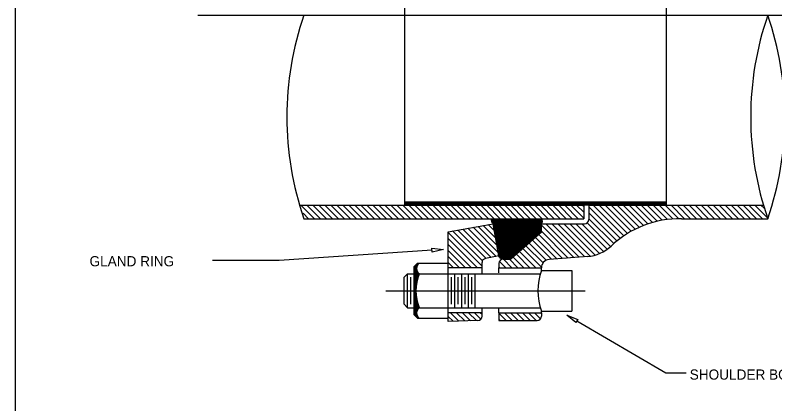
# Model space of a CAD drawing. Extents: x 2147138 to 2147698, y 2147153 to 2147515.
# Drawn here: x 2147558.3 to 2147647.9, y 2147251.8 to 2147297.7 of the extents above; entities that cross this region are included whole.
import ezdxf

# ---------------------------------------------------------------- set-up
doc = ezdxf.new("R2010")
doc.units = 0
for name, color, linetype in [('EQPM', 7, 'Continuous'), ('G-ANNO-TEXT-LW10', 7, 'Continuous'), ('G-DETL-CNTR', 7, 'Continuous'), ('G-DETL-LW10', 7, 'Continuous'), ('G-DETL-PATT', 7, 'Continuous'), ('PATTERN_CLASS', 7, 'Continuous')]:
    doc.layers.add(name, color=color, linetype=linetype)

msp = doc.modelspace()

# ---------------------------------------------------------------- linework, layer by layer
at = {"layer": 'EQPM'}
for p, q in [((2147604.195, 2147275.672), (2147604.195, 2147275.272)), ((2147604.195, 2147275.672), (2147635.045, 2147275.672)), ((2147604.195, 2147275.654), (2147635.045, 2147275.654)), ((2147604.195, 2147275.604), (2147635.045, 2147275.604)), ((2147604.195, 2147275.554), (2147635.045, 2147275.554)), ((2147604.195, 2147275.504), (2147635.045, 2147275.504)), ((2147604.195, 2147275.454), (2147635.045, 2147275.454)), ((2147604.195, 2147275.404), (2147635.045, 2147275.404)), ((2147604.195, 2147275.354), (2147635.045, 2147275.354)), ((2147604.195, 2147275.304), (2147635.045, 2147275.304)), ((2147625.93, 2147275.272), (2147625.33, 2147275.272)), ((2147635.045, 2147275.672), (2147635.045, 2147275.272))]:
    msp.add_line(p, q, dxfattribs=at)
at = {"layer": 'G-ANNO-TEXT-LW10'}
for p, q in [((2147607.435, 2147269.953), (2147589.386, 2147268.72)), ((2147589.386, 2147268.72), (2147581.522, 2147268.72)), ((2147624.501, 2147261.603), (2147635.011, 2147255.478)), ((2147635.011, 2147255.478), (2147637.397, 2147255.478))]:
    msp.add_line(p, q, dxfattribs=at)
for points in [[(2147607.42, 2147270.175), (2147608.767, 2147270.044), (2147607.45, 2147269.731)], [(2147624.389, 2147261.41), (2147623.347, 2147262.275), (2147624.613, 2147261.795)]]:
    msp.add_lwpolyline(points, close=True, dxfattribs=at)
at = {"layer": 'G-DETL-CNTR'}
for p, q in [((2147579.795, 2147297.672), (2147660.381, 2147297.672)), ((2147601.998, 2147265.172), (2147625.503, 2147265.172))]:
    msp.add_line(p, q, dxfattribs=at)
at = {"layer": 'G-DETL-LW10'}
for p, q in [((2147591.791, 2147275.272), (2147625.33, 2147275.272)), ((2147625.33, 2147275.272), (2147625.33, 2147273.672)), ((2147625.93, 2147275.272), (2147646.527, 2147275.272)), ((2147625.93, 2147275.272), (2147625.93, 2147273.572)), ((2147592.302, 2147273.672), (2147625.33, 2147273.672)), ((2147609.33, 2147272.135), (2147614.663, 2147273.075)), ((2147614.459, 2147273.559), (2147614.464, 2147273.581)), ((2147614.459, 2147273.521), (2147614.459, 2147273.559)), ((2147614.466, 2147273.467), (2147614.459, 2147273.521)), ((2147614.464, 2147273.581), (2147614.478, 2147273.594)), ((2147614.479, 2147273.36), (2147614.466, 2147273.467)), ((2147614.478, 2147273.594), (2147614.498, 2147273.597)), ((2147614.504, 2147273.279), (2147614.479, 2147273.36)), ((2147614.498, 2147273.597), (2147614.519, 2147273.598)), ((2147614.539, 2147273.202), (2147614.504, 2147273.279)), ((2147614.519, 2147273.598), (2147620.341, 2147273.598)), ((2147614.59, 2147273.143), (2147614.539, 2147273.202)), ((2147614.628, 2147273.113), (2147614.59, 2147273.143)), ((2147614.671, 2147273.1), (2147614.628, 2147273.113)), ((2147615.33, 2147269.292), (2147614.663, 2147273.075)), ((2147615.357, 2147269.276), (2147614.671, 2147273.1)), ((2147620.39, 2147273.179), (2147620.304, 2147273.084)), ((2147620.304, 2147273.084), (2147620.305, 2147272.084)), ((2147620.33, 2147273.072), (2147625.43, 2147273.072)), ((2147620.33, 2147272.072), (2147620.33, 2147273.072)), ((2147620.341, 2147273.598), (2147620.395, 2147273.52)), ((2147620.422, 2147273.261), (2147620.39, 2147273.179)), ((2147620.395, 2147273.52), (2147620.431, 2147273.388)), ((2147620.431, 2147273.388), (2147620.422, 2147273.261)), ((2147636.86, 2147273.672), (2147647.038, 2147273.672)), ((2147609.33, 2147267.892), (2147609.33, 2147272.135)), ((2147620.305, 2147272.084), (2147616.725, 2147268.907)), ((2147620.33, 2147272.072), (2147616.73, 2147268.892)), ((2147615.33, 2147269.292), (2147613.732, 2147268.973)), ((2147615.314, 2147269.268), (2147615.357, 2147269.276)), ((2147615.314, 2147269.224), (2147615.314, 2147269.268)), ((2147615.334, 2147269.165), (2147615.314, 2147269.224)), ((2147615.373, 2147269.098), (2147615.334, 2147269.165)), ((2147615.456, 2147269.027), (2147615.373, 2147269.098)), ((2147615.559, 2147268.964), (2147615.456, 2147269.027)), ((2147615.642, 2147268.928), (2147615.559, 2147268.964)), ((2147615.717, 2147268.908), (2147615.642, 2147268.928)), ((2147616.725, 2147268.907), (2147615.717, 2147268.908)), ((2147615.83, 2147268.892), (2147616.73, 2147268.892)), ((2147625.793, 2147269.207), (2147621.252, 2147268.865)), ((2147605.33, 2147268.022), (2147605.73, 2147268.422)), ((2147605.33, 2147262.322), (2147605.33, 2147268.022)), ((2147605.73, 2147268.422), (2147609.33, 2147268.422)), ((2147609.33, 2147261.922), (2147609.33, 2147268.422)), ((2147613.33, 2147267.892), (2147609.33, 2147267.892)), ((2147613.33, 2147267.892), (2147613.33, 2147268.483)), ((2147613.33, 2147267.172), (2147613.33, 2147267.892)), ((2147615.33, 2147268.392), (2147615.33, 2147267.892)), ((2147615.33, 2147267.892), (2147620.33, 2147267.892)), ((2147615.33, 2147267.292), (2147615.33, 2147267.892)), ((2147620.33, 2147267.572), (2147620.33, 2147267.868)), ((2147604.13, 2147266.772), (2147604.53, 2147267.172)), ((2147604.53, 2147263.172), (2147604.53, 2147267.172)), ((2147604.53, 2147267.172), (2147605.33, 2147267.172)), ((2147605.93, 2147267.172), (2147609.33, 2147267.172)), ((2147609.33, 2147267.172), (2147620.206, 2147267.172)), ((2147610.13, 2147263.172), (2147610.13, 2147267.172)), ((2147610.93, 2147263.172), (2147610.93, 2147267.172)), ((2147611.73, 2147263.172), (2147611.73, 2147267.172)), ((2147612.53, 2147263.172), (2147612.53, 2147267.172)), ((2147620.33, 2147267.572), (2147623.93, 2147267.572)), ((2147623.93, 2147267.572), (2147623.93, 2147262.772)), ((2147604.13, 2147263.572), (2147604.13, 2147266.772)), ((2147604.93, 2147263.572), (2147604.93, 2147266.772)), ((2147609.73, 2147263.572), (2147609.73, 2147266.772)), ((2147610.53, 2147263.572), (2147610.53, 2147266.772)), ((2147611.33, 2147263.572), (2147611.33, 2147266.772)), ((2147612.13, 2147263.572), (2147612.13, 2147266.772)), ((2147604.53, 2147263.172), (2147604.13, 2147263.572)), ((2147604.53, 2147263.172), (2147605.33, 2147263.172)), ((2147605.33, 2147262.322), (2147605.73, 2147261.922)), ((2147605.93, 2147263.172), (2147609.33, 2147263.172)), ((2147609.33, 2147263.172), (2147620.206, 2147263.172)), ((2147613.33, 2147262.572), (2147609.33, 2147262.572)), ((2147609.33, 2147261.552), (2147609.33, 2147262.572)), ((2147613.33, 2147262.572), (2147613.33, 2147263.172)), ((2147613.33, 2147262.158), (2147613.33, 2147262.572)), ((2147615.33, 2147262.572), (2147615.33, 2147263.172)), ((2147615.33, 2147262.572), (2147620.33, 2147262.572)), ((2147615.33, 2147262.572), (2147615.33, 2147261.672)), ((2147620.33, 2147262.572), (2147620.33, 2147262.772)), ((2147620.33, 2147262.772), (2147623.93, 2147262.772)), ((2147620.33, 2147262.572), (2147620.33, 2147262.172)), ((2147605.73, 2147261.922), (2147609.33, 2147261.922)), ((2147612.845, 2147261.658), (2147609.33, 2147261.552)), ((2147615.33, 2147261.672), (2147619.83, 2147261.672))]:
    msp.add_line(p, q, dxfattribs=at)
for centre, radius, start, end in [((2147627.142, 2147285.672), 36.849, 160.99467, 199.00533), ((2147627.142, 2147285.672), 36.849, 160.99467, 199.00533), ((2147681.878, 2147285.672), 36.849, 160.99467, 199.00533), ((2147612.198, 2147285.672), 36.849, 340.99467, 19.00533), ((2147625.43, 2147273.572), 0.5, 270, 0), ((2147636.69, 2147261.787), 11.886, 89.17883, 133.23579), ((2147625.43, 2147273.692), 4.5, 274.61829, 313.84535), ((2147613.83, 2147268.483), 0.5, 101.30993, 180), ((2147615.83, 2147268.392), 0.5, 90, 180), ((2147621.33, 2147267.868), 1, 94.4928, 180), ((2147606.401, 2147267.797), 0.783, 127.00306, 232.99694), ((2147610.73, 2147265.172), 5.2, 157.38014, 202.61986), ((2147627.33, 2147265.172), 7.4, 161.07536, 198.92464), ((2147606.401, 2147262.547), 0.783, 127.00306, 232.99694), ((2147612.83, 2147262.158), 0.5, 271.71836, 0), ((2147619.83, 2147262.172), 0.5, 270, 0)]:
    msp.add_arc(centre, radius, start, end, dxfattribs=at)
at = {"layer": 'G-DETL-PATT'}
for p, q in [((2147604.195, 2147319.672), (2147604.195, 2147275.672)), ((2147635.045, 2147319.672), (2147635.045, 2147275.653)), ((2147591.967, 2147275.272), (2147593.567, 2147273.672)), ((2147592.675, 2147275.272), (2147594.275, 2147273.672)), ((2147593.382, 2147275.272), (2147594.982, 2147273.672)), ((2147594.089, 2147275.272), (2147595.689, 2147273.672)), ((2147594.796, 2147275.272), (2147596.396, 2147273.672)), ((2147595.503, 2147275.272), (2147597.103, 2147273.672)), ((2147596.21, 2147275.272), (2147597.81, 2147273.672)), ((2147596.917, 2147275.272), (2147598.517, 2147273.672)), ((2147597.624, 2147275.272), (2147599.224, 2147273.672)), ((2147598.331, 2147275.272), (2147599.931, 2147273.672)), ((2147599.039, 2147275.272), (2147600.639, 2147273.672)), ((2147599.746, 2147275.272), (2147601.346, 2147273.672)), ((2147600.453, 2147275.272), (2147602.053, 2147273.672)), ((2147601.16, 2147275.272), (2147602.76, 2147273.672)), ((2147601.867, 2147275.272), (2147603.467, 2147273.672)), ((2147602.574, 2147275.272), (2147604.174, 2147273.672)), ((2147603.281, 2147275.272), (2147604.881, 2147273.672)), ((2147603.988, 2147275.272), (2147605.588, 2147273.672)), ((2147604.695, 2147275.272), (2147606.295, 2147273.672)), ((2147605.403, 2147275.272), (2147607.003, 2147273.672)), ((2147606.11, 2147275.272), (2147607.71, 2147273.672)), ((2147606.817, 2147275.272), (2147608.417, 2147273.672)), ((2147607.524, 2147275.272), (2147609.124, 2147273.672)), ((2147608.231, 2147275.272), (2147609.831, 2147273.672)), ((2147608.938, 2147275.272), (2147610.538, 2147273.672)), ((2147609.645, 2147275.272), (2147611.245, 2147273.672)), ((2147610.352, 2147275.272), (2147611.952, 2147273.672)), ((2147611.059, 2147275.272), (2147612.659, 2147273.672)), ((2147611.766, 2147275.272), (2147613.366, 2147273.672)), ((2147612.474, 2147275.272), (2147614.074, 2147273.672)), ((2147613.181, 2147275.272), (2147614.781, 2147273.672)), ((2147613.888, 2147275.272), (2147615.488, 2147273.672)), ((2147614.595, 2147275.272), (2147616.195, 2147273.672)), ((2147615.302, 2147275.272), (2147616.902, 2147273.672)), ((2147616.009, 2147275.272), (2147617.609, 2147273.672)), ((2147616.716, 2147275.272), (2147618.316, 2147273.672)), ((2147617.423, 2147275.272), (2147619.023, 2147273.672)), ((2147618.13, 2147275.272), (2147619.73, 2147273.672)), ((2147618.838, 2147275.272), (2147620.438, 2147273.672)), ((2147619.545, 2147275.272), (2147621.145, 2147273.672)), ((2147620.252, 2147275.272), (2147621.852, 2147273.672)), ((2147620.959, 2147275.272), (2147622.559, 2147273.672)), ((2147621.666, 2147275.272), (2147623.266, 2147273.672)), ((2147622.373, 2147275.272), (2147623.973, 2147273.672)), ((2147623.08, 2147275.272), (2147624.68, 2147273.672)), ((2147623.787, 2147275.272), (2147625.33, 2147273.729)), ((2147624.494, 2147275.272), (2147625.33, 2147274.437)), ((2147625.202, 2147275.272), (2147625.33, 2147275.144)), ((2147629.645, 2147271.361), (2147625.93, 2147275.077)), ((2147630.061, 2147271.653), (2147626.442, 2147275.272)), ((2147630.491, 2147271.93), (2147627.149, 2147275.272)), ((2147630.938, 2147272.19), (2147627.856, 2147275.272)), ((2147631.402, 2147272.433), (2147628.563, 2147275.272)), ((2147631.884, 2147272.659), (2147629.27, 2147275.272)), ((2147632.383, 2147272.866), (2147629.977, 2147275.272)), ((2147632.902, 2147273.054), (2147630.684, 2147275.272)), ((2147633.442, 2147273.221), (2147631.391, 2147275.272)), ((2147634.004, 2147273.366), (2147632.098, 2147275.272)), ((2147634.591, 2147273.487), (2147632.805, 2147275.272)), ((2147635.205, 2147273.58), (2147633.513, 2147275.272)), ((2147635.848, 2147273.644), (2147634.22, 2147275.272)), ((2147636.527, 2147273.673), (2147634.927, 2147275.272)), ((2147637.234, 2147273.672), (2147635.634, 2147275.272)), ((2147637.941, 2147273.672), (2147636.341, 2147275.272)), ((2147638.648, 2147273.672), (2147637.048, 2147275.272)), ((2147639.355, 2147273.672), (2147637.755, 2147275.272)), ((2147640.062, 2147273.672), (2147638.462, 2147275.272)), ((2147640.769, 2147273.672), (2147639.169, 2147275.272)), ((2147641.477, 2147273.672), (2147639.877, 2147275.272)), ((2147642.184, 2147273.672), (2147640.584, 2147275.272)), ((2147642.891, 2147273.672), (2147641.291, 2147275.272)), ((2147643.598, 2147273.672), (2147641.998, 2147275.272)), ((2147644.305, 2147273.672), (2147642.705, 2147275.272)), ((2147645.012, 2147273.672), (2147643.412, 2147275.272)), ((2147645.719, 2147273.672), (2147644.119, 2147275.272)), ((2147646.426, 2147273.672), (2147644.826, 2147275.272)), ((2147646.988, 2147273.818), (2147645.533, 2147275.272)), ((2147646.65, 2147274.863), (2147646.241, 2147275.272)), ((2147592.23, 2147274.303), (2147592.86, 2147273.672)), ((2147629.246, 2147271.054), (2147625.93, 2147274.369)), ((2147614.582, 2147273.598), (2147614.582, 2147273.151)), ((2147614.707, 2147273.598), (2147614.707, 2147272.898)), ((2147614.832, 2147273.598), (2147614.832, 2147272.202)), ((2147614.957, 2147273.598), (2147614.957, 2147271.506)), ((2147615.082, 2147273.598), (2147615.082, 2147270.809)), ((2147615.207, 2147273.598), (2147615.207, 2147270.113)), ((2147615.332, 2147273.598), (2147615.332, 2147269.416)), ((2147615.457, 2147273.598), (2147615.457, 2147269.026)), ((2147615.582, 2147273.598), (2147615.582, 2147268.954)), ((2147615.707, 2147273.598), (2147615.707, 2147268.911)), ((2147615.832, 2147273.598), (2147615.832, 2147268.908)), ((2147615.957, 2147273.598), (2147615.957, 2147268.908)), ((2147616.082, 2147273.598), (2147616.082, 2147268.908)), ((2147616.207, 2147273.598), (2147616.207, 2147268.908)), ((2147616.332, 2147273.598), (2147616.332, 2147268.908)), ((2147616.457, 2147273.598), (2147616.457, 2147268.908)), ((2147616.582, 2147273.598), (2147616.582, 2147268.907)), ((2147616.707, 2147273.598), (2147616.707, 2147268.907)), ((2147616.832, 2147273.598), (2147616.832, 2147269.002)), ((2147616.957, 2147273.598), (2147616.957, 2147269.113)), ((2147617.082, 2147273.598), (2147617.082, 2147269.224)), ((2147617.207, 2147273.598), (2147617.207, 2147269.335)), ((2147617.332, 2147273.598), (2147617.332, 2147269.446)), ((2147617.457, 2147273.598), (2147617.457, 2147269.557)), ((2147617.582, 2147273.598), (2147617.582, 2147269.668)), ((2147617.707, 2147273.598), (2147617.707, 2147269.778)), ((2147617.832, 2147273.598), (2147617.832, 2147269.889)), ((2147617.957, 2147273.598), (2147617.957, 2147270)), ((2147618.082, 2147273.598), (2147618.082, 2147270.111)), ((2147618.207, 2147273.598), (2147618.207, 2147270.222)), ((2147618.332, 2147273.598), (2147618.332, 2147270.333)), ((2147618.457, 2147273.598), (2147618.457, 2147270.444)), ((2147618.582, 2147273.598), (2147618.582, 2147270.555)), ((2147618.707, 2147273.598), (2147618.707, 2147270.666)), ((2147618.832, 2147273.598), (2147618.832, 2147270.777)), ((2147618.957, 2147273.598), (2147618.957, 2147270.888)), ((2147619.082, 2147273.598), (2147619.082, 2147270.999)), ((2147619.207, 2147273.598), (2147619.207, 2147271.11)), ((2147619.332, 2147273.598), (2147619.332, 2147271.22)), ((2147619.457, 2147273.598), (2147619.457, 2147271.331)), ((2147619.582, 2147273.598), (2147619.582, 2147271.442)), ((2147619.707, 2147273.598), (2147619.707, 2147271.553)), ((2147619.832, 2147273.598), (2147619.832, 2147271.664)), ((2147619.957, 2147273.598), (2147619.957, 2147271.775)), ((2147620.082, 2147273.598), (2147620.082, 2147271.886)), ((2147620.207, 2147273.598), (2147620.207, 2147271.997)), ((2147620.332, 2147273.598), (2147620.332, 2147273.115)), ((2147624.803, 2147269.132), (2147620.863, 2147273.072)), ((2147625.461, 2147269.182), (2147621.57, 2147273.072)), ((2147626.106, 2147269.244), (2147622.278, 2147273.072)), ((2147626.686, 2147269.371), (2147622.985, 2147273.072)), ((2147627.206, 2147269.558), (2147623.692, 2147273.072)), ((2147627.678, 2147269.794), (2147624.399, 2147273.072)), ((2147628.105, 2147270.074), (2147625.106, 2147273.072)), ((2147628.491, 2147270.394), (2147625.72, 2147273.165)), ((2147628.861, 2147270.732), (2147625.93, 2147273.662)), ((2147609.861, 2147272.228), (2147613.383, 2147268.706)), ((2147610.462, 2147272.334), (2147613.808, 2147268.988)), ((2147611.063, 2147272.44), (2147614.398, 2147269.106)), ((2147611.664, 2147272.546), (2147614.987, 2147269.224)), ((2147612.265, 2147272.652), (2147615.267, 2147269.65)), ((2147612.866, 2147272.758), (2147615.116, 2147270.509)), ((2147613.468, 2147272.864), (2147614.964, 2147271.367)), ((2147614.069, 2147272.97), (2147614.813, 2147272.226)), ((2147624.146, 2147269.083), (2147620.33, 2147272.898)), ((2147623.488, 2147269.033), (2147620.33, 2147272.191)), ((2147609.33, 2147272.052), (2147613.33, 2147268.052)), ((2147609.33, 2147271.345), (2147612.783, 2147267.892)), ((2147622.173, 2147268.934), (2147619.642, 2147271.465)), ((2147622.831, 2147268.984), (2147620.018, 2147271.797)), ((2147609.33, 2147270.638), (2147612.075, 2147267.892)), ((2147620.525, 2147268.461), (2147618.516, 2147270.47)), ((2147620.915, 2147268.778), (2147618.892, 2147270.802)), ((2147621.516, 2147268.885), (2147619.267, 2147271.133)), ((2147609.33, 2147269.93), (2147611.368, 2147267.892)), ((2147619.679, 2147267.892), (2147617.765, 2147269.807)), ((2147620.333, 2147267.946), (2147618.141, 2147270.138)), ((2147609.33, 2147269.223), (2147610.661, 2147267.892)), ((2147615.332, 2147269.271), (2147615.332, 2147269.17)), ((2147616.144, 2147267.892), (2147615.396, 2147268.64)), ((2147616.851, 2147267.892), (2147615.851, 2147268.892)), ((2147617.558, 2147267.892), (2147616.558, 2147268.892)), ((2147618.265, 2147267.892), (2147617.014, 2147269.143)), ((2147618.972, 2147267.892), (2147617.39, 2147269.475)), ((2147605.357, 2147268.049), (2147605.357, 2147265.172)), ((2147605.407, 2147268.099), (2147605.407, 2147265.172)), ((2147605.457, 2147268.149), (2147605.457, 2147265.172)), ((2147605.507, 2147268.199), (2147605.507, 2147265.172)), ((2147605.557, 2147268.249), (2147605.557, 2147265.7)), ((2147605.607, 2147268.299), (2147605.607, 2147266.063)), ((2147605.657, 2147268.349), (2147605.657, 2147268.04)), ((2147605.707, 2147268.399), (2147605.707, 2147268.159)), ((2147605.757, 2147268.422), (2147605.757, 2147268.242)), ((2147605.807, 2147268.422), (2147605.807, 2147268.307)), ((2147605.857, 2147268.422), (2147605.857, 2147268.36)), ((2147605.907, 2147268.422), (2147605.907, 2147268.404)), ((2147609.33, 2147268.516), (2147609.954, 2147267.892)), ((2147615.437, 2147267.892), (2147615.33, 2147267.999)), ((2147605.657, 2147267.555), (2147605.657, 2147266.314)), ((2147605.707, 2147267.436), (2147605.707, 2147266.517)), ((2147605.757, 2147267.353), (2147605.757, 2147266.692)), ((2147605.807, 2147267.288), (2147605.807, 2147266.846)), ((2147605.857, 2147267.235), (2147605.857, 2147266.987)), ((2147605.907, 2147267.191), (2147605.907, 2147267.116)), ((2147605.357, 2147265.172), (2147605.357, 2147262.296)), ((2147605.407, 2147265.172), (2147605.407, 2147262.246)), ((2147605.457, 2147265.172), (2147605.457, 2147262.196)), ((2147605.507, 2147265.172), (2147605.507, 2147262.146)), ((2147605.557, 2147264.645), (2147605.557, 2147262.096)), ((2147605.607, 2147264.282), (2147605.607, 2147262.046)), ((2147605.657, 2147264.031), (2147605.657, 2147262.79)), ((2147605.707, 2147263.828), (2147605.707, 2147262.909)), ((2147605.757, 2147263.653), (2147605.757, 2147262.992)), ((2147605.807, 2147263.498), (2147605.807, 2147263.057)), ((2147605.857, 2147263.358), (2147605.857, 2147263.11)), ((2147605.907, 2147263.229), (2147605.907, 2147263.154)), ((2147609.617, 2147262.572), (2147610.599, 2147261.59)), ((2147610.324, 2147262.572), (2147611.286, 2147261.611)), ((2147611.031, 2147262.572), (2147611.972, 2147261.632)), ((2147611.739, 2147262.572), (2147612.659, 2147261.652)), ((2147612.446, 2147262.572), (2147613.199, 2147261.82)), ((2147613.153, 2147262.572), (2147613.33, 2147262.395)), ((2147615.33, 2147262.516), (2147616.174, 2147261.672)), ((2147615.981, 2147262.572), (2147616.881, 2147261.672)), ((2147616.688, 2147262.572), (2147617.588, 2147261.672)), ((2147617.395, 2147262.572), (2147618.295, 2147261.672)), ((2147618.103, 2147262.572), (2147619.003, 2147261.672)), ((2147618.81, 2147262.572), (2147619.71, 2147261.672)), ((2147619.517, 2147262.572), (2147620.224, 2147261.865)), ((2147620.224, 2147262.572), (2147620.33, 2147262.466)), ((2147605.657, 2147262.305), (2147605.657, 2147261.996)), ((2147605.707, 2147262.186), (2147605.707, 2147261.946)), ((2147605.757, 2147262.103), (2147605.757, 2147261.922)), ((2147605.807, 2147262.038), (2147605.807, 2147261.922)), ((2147605.857, 2147261.985), (2147605.857, 2147261.922)), ((2147605.907, 2147261.941), (2147605.907, 2147261.922)), ((2147609.33, 2147262.152), (2147609.913, 2147261.57)), ((2147615.33, 2147261.809), (2147615.467, 2147261.672))]:
    msp.add_line(p, q, dxfattribs=at)
at = {"layer": 'PATTERN_CLASS'}
msp.add_line((2147558.253, 2147344.122), (2147558.253, 2147215.016), dxfattribs=at)

# ---------------------------------------------------------------- texts
at = {"layer": 'G-ANNO-TEXT-LW10'}
for s, p in [('GLAND RING', (2147567.023, 2147268.054)), ('SHOULDER BOLTS', (2147637.832, 2147254.686))]:
    msp.add_text(s, height=1.2, dxfattribs=at).set_placement(p)

doc.saveas('drawing.dxf')
